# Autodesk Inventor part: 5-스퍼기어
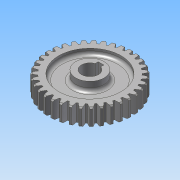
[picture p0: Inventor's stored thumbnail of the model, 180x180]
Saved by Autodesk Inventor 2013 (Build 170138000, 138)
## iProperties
Created: 2013-08
Part Number: 5-스퍼기어
Material: 강
Document SubType Name: Modeling
Designer: 한국산업디자인학원
Categories: <?xml version="1.0" encoding="UTF-16"?> <MemberInstance><Categories><FamilyTemplate><FamilyTemplateParameter ValueType="xs:double" Id="1" ObjectReferenceKey="da
Density: 1 g/cm^3
CustomPartVersion: 1
Author: 한국산업디자인학원
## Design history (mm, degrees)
sketch "Sketch1"
  geometry: C1 r 37 at (0, 0)
  constraints: 1 centre point
  dimensions: "d0" = 74 diameter of C1 (= da_da)
extrude "Extrusion1" new body sketch "Sketch1" distance "d1" = 15 (= da_b); taper "d2" = 0 deg
chamfer "모따기1" distance "d49" = 1; stored, may be unused: second distance "d50" = 2, angle "d51" = 45 deg
workplane "Work Plane2"
feature "피치 지름" dims "d4" = 10, "d5" = 0
workplane "Work Plane8"
workplane "Work Plane9"
feature "스퍼 기어" dims "da_b" = 15, "da_d" = 70, "da_aw" = 70, "da_da" = 74, "da_df" = 65, "da_dw" = 70, angle "da_beta" = 0 deg, "da_lefttooth" = 0, "da_righttooth" = 0
node "작업 평면11"
sketch "스케치4"
  geometry: C1 r 12.5 at (0, 0); 1 further point
  constraints: 1 centre point, 1 coincident
  dimensions: "d53" = 25 diameter of C1
extrude "돌출2" join sketch "스케치4" distance "d55" = 31; taper "d56" = 0 deg
sketch "스케치5"
  geometry: L1 (-2.5, 7.071)-(-2.5, 9.8); L2 (-2.5, 9.8)-(2.5, 9.8); L3 (2.5, 9.8)-(2.5, 7.071); C1 r 12.5 at (0, 0) reference; A1 r 7.5 centre (0, 0) between (-2.5, 7.071) and (2.5, 7.071); 1 further point
  constraints: 6 end point, 2 point on circle, 1 centre point, 1 coincident, 1 midpoint, 1 parallel, 1 perpendicular, 1 vertical, 1 vertical alignment
  dimensions: "d57" = 17.3 dimension on A1 L2; "d59" = 15 diameter of A1; "d60" = 5 distance of L1.end L2.end
extrude "돌출3" cut sketch "스케치5" stored distance "d61" = 31; taper "d62" = 0 deg
sketch "스케치6"
  geometry: C1 r 12.5 at (0, 0) reference; C2 r 27.5 at (0, 0); C3 r 12.5 at (0, 0) reference; A1 r 36 centre (0, 0) between (-5.215, 35.62) and (-7.633, 35.181) reference
  constraints: 1 centre point, 1 coincident
  dimensions: "d63" = 55 diameter of C2
extrude "돌출4" cut sketch "스케치6" distance "d65" = 5; taper "d66" = 0 deg
node "작업 평면12"
fillet "모깎기1" dims "d67" = 3
body "Solid1"
mirror "대칭1"
sketch "Sketch2"
  geometry: C1 r 37 at (0, 0) reference; C2 r 35 at (0, 0)
  constraints: 1 centre point, 1 coincident
  dimensions: "d3" = 70 diameter of C2 (= da_dw)
body "Srf1"
other parameters: "d17" = 0, "d34" = 0.8976 (computed from da_z), "d39" = 0, "d41" = 0, "d47" = 0, "d48" = 0, "d52" = 3
